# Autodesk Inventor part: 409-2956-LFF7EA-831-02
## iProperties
Created: 2010-09
Part Number: 409-2956-LFF7EA-831-02
Material: 3/8"OD TUBE - SS
Document SubType Name: Modeling
Designer: S. Boerckel
Engineer: Steve Boerckel
Mass: 166.544 g
Surface Area: 342.312 cm^2
Volume: 20.6119 cm^3
Density: 8.08 g/cm^3
Description: LOW PRESSURE GAUGE TUBE
LGTH: 21.434 in
Author: S. Boerckel
Revision Number: 0
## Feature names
1. Sweep1
